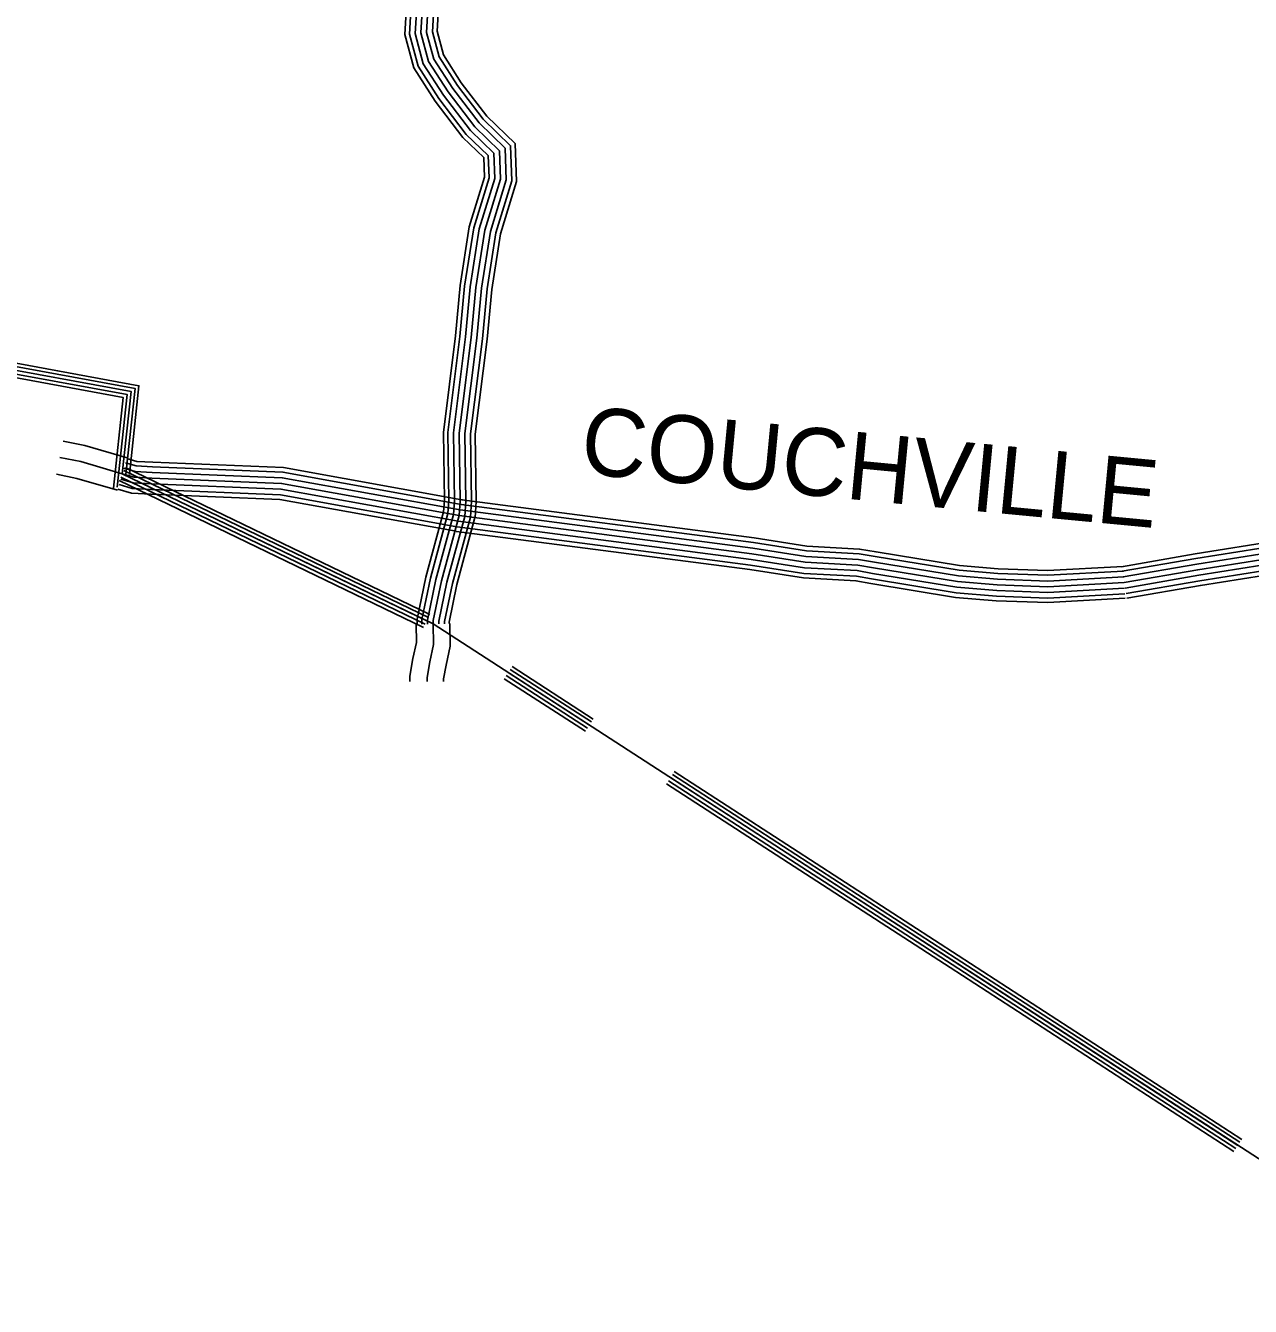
# Model space of a CAD drawing. Extents: x 1788175 to 1969470, y 584502 to 738744.
# Drawn here: x 1829254 to 1835948, y 628222 to 635221 of the extents above; entities that cross this region are included whole.
import ezdxf

# ---------------------------------------------------------------- set-up
doc = ezdxf.new("R2010")
doc.units = 0
for name, color, linetype in [('DESIGN - ROW - Right-of-Way and Easement Labels', 7, 'Continuous'), ('SURVEY - CONTOURS - Index with Text', 7, 'Continuous'), ('SURVEY - DRAINAGE - Natural Features', 7, 'Continuous')]:
    doc.layers.add(name, color=color, linetype=linetype)

msp = doc.modelspace()

# ---------------------------------------------------------------- linework, layer by layer
at = {"layer": 'SURVEY - CONTOURS - Index with Text'}
for points in [[(1831684.4, 632535.7), (1831691.1, 632621.7), (1831685.8, 632990.2), (1831750.6, 633509.5), (1831776, 633782.8), (1831824.1, 634089), (1831911.3, 634373.6), (1831904.6, 634564.9), (1831755, 634709.7), (1831613.8, 634894.6), (1831513.1, 635051.2), (1831476.8, 635187.8), (1831491.4, 635441.6)], [(1831709.9, 632532.3), (1831716.8, 632620.9), (1831711.5, 632988.8), (1831776.2, 633506.8), (1831801.5, 633779.6), (1831849.3, 634083.2), (1831937.1, 634370.2), (1831930, 634576.2), (1831774.3, 634726.9), (1831634.9, 634909.4), (1831536.9, 635061.7), (1831502.7, 635190.4), (1831517.7, 635449.9)], [(1831537.4, 632563.9), (1831542.3, 632626.4), (1831536.9, 632998.4), (1831602.7, 633525.6), (1831628.4, 633801.3), (1831678.8, 634122.5), (1831761.8, 634393.3), (1831758.1, 634499.8), (1831643.6, 634610.6), (1831492, 634809.1), (1831375.4, 634990.4), (1831327, 635172.6), (1831339.7, 635393.6)], [(1831561.5, 632554.4), (1831567, 632625.6), (1831561.7, 632997), (1831627.3, 633523), (1831652.9, 633798.2), (1831703, 634116.9), (1831786.6, 634390), (1831782.4, 634510.6), (1831662.1, 634627.1), (1831512.3, 634823.3), (1831398.3, 635000.5), (1831351.9, 635175.1), (1831364.9, 635401.6)], [(1831592.1, 632549), (1831598, 632624.7), (1831592.7, 632995.3), (1831658.1, 633519.6), (1831683.7, 633794.3), (1831733.3, 634109.9), (1831817.8, 634385.9), (1831813, 634524.2), (1831685.3, 634647.7), (1831537.6, 634841.1), (1831427, 635013.2), (1831383.1, 635178.3), (1831396.5, 635411.6)], [(1831622.8, 632543.7), (1831629.1, 632623.7), (1831623.7, 632993.6), (1831688.9, 633516.2), (1831714.4, 633790.5), (1831763.6, 634103), (1831848.9, 634381.8), (1831843.5, 634537.7), (1831708.6, 634668.4), (1831563, 634858.9), (1831455.7, 635025.9), (1831414.4, 635181.5), (1831428.2, 635421.6)], [(1831622.8, 632543.7), (1831629.1, 632623.7), (1831623.7, 632993.6), (1831688.9, 633516.2), (1831714.4, 633790.5), (1831763.6, 634103), (1831848.9, 634381.8), (1831843.5, 634537.7), (1831708.6, 634668.4), (1831563, 634858.9), (1831455.7, 635025.9), (1831414.4, 635181.5), (1831428.2, 635421.6)], [(1831653.5, 632538.4), (1831660.1, 632622.7), (1831654.8, 632991.9), (1831719.8, 633512.9), (1831745.2, 633786.7), (1831793.8, 634096), (1831880.1, 634377.7), (1831874.1, 634551.3), (1831731.8, 634689.1), (1831588.4, 634876.8), (1831484.4, 635038.5), (1831445.6, 635184.6), (1831459.8, 635431.6)], [(1829458.2, 632950.6), (1829577.6, 632926.8), (1829807.7, 632859.1)], [(1829440.5, 632861.6), (1829555.9, 632838.6), (1829782.1, 632772)], [(1829806.6, 632855.2), (1829861.1, 632839.2), (1829948.2, 632834.6), (1830662.2, 632805.8), (1831637.9, 632629.1)], [(1829790.9, 632801.8), (1829851.6, 632783.9), (1829945.6, 632778.9), (1830656, 632750.3), (1831628, 632574.3)], [(1829799.6, 632831.5), (1829856.9, 632814.7), (1829947, 632809.9), (1830659.5, 632781.2), (1831633.5, 632604.8)], [(1829422.1, 632769.1), (1829533.4, 632747), (1829755.5, 632681.6)], [(1829764.6, 632712.6), (1829835.8, 632691.6), (1829941.2, 632686), (1830645.8, 632657.6), (1831611.4, 632482.8)], [(1829773.4, 632742.3), (1829841.1, 632722.4), (1829942.7, 632717), (1830649.2, 632688.5), (1831616.9, 632513.3)], [(1829782.1, 632772), (1829846.3, 632753.1), (1829944.1, 632748), (1830652.6, 632719.4), (1831622.4, 632543.8)], [(1829782.1, 632772), (1829846.3, 632753.1), (1829944.1, 632748), (1830652.6, 632719.4), (1831622.4, 632543.8)], [(1841380.2, 632093.3), (1840922.1, 632170.4), (1840362.2, 632274.4), (1840090.4, 632334.8), (1839883.1, 632440.9), (1839700.9, 632519), (1839594.2, 632542.1), (1839454.9, 632534.9), (1839250.1, 632485.8), (1838878.8, 632342.6), (1838808, 632325.5), (1838675.8, 632331.9), (1838556, 632355.9), (1838187.8, 632548.5), (1837854.1, 632680.8), (1837731.3, 632713.8), (1837557.4, 632724.3), (1837402.1, 632698.8), (1837098.5, 632599.5), (1836637.1, 632513.8), (1836103.9, 632406.8), (1835646.4, 632334.4), (1835243.3, 632264.3)], [(1829757.4, 632687.9), (1829831.4, 632666.1), (1829940, 632660.3), (1830643, 632632), (1831606.8, 632457.5)], [(1841376.3, 632067.9), (1840917.6, 632145.1), (1840357, 632249.2), (1840081.6, 632310.4), (1839872.1, 632417.6), (1839693.1, 632494.4), (1839592.1, 632516.2), (1839458.6, 632509.3), (1839257.7, 632461.1), (1838886.4, 632318), (1838810.4, 632299.6), (1838672.7, 632306.3), (1838547.3, 632331.4), (1838177.1, 632525.1), (1837846, 632656.3), (1837727.1, 632688.3), (1837558.7, 632698.5), (1837408.2, 632673.8), (1837104.9, 632574.6), (1836641.9, 632488.6), (1836108.5, 632381.4), (1835650.6, 632309), (1835247.7, 632238.9)], [(1841371.5, 632037.3), (1840912.2, 632114.6), (1840350.8, 632218.8), (1840071, 632281), (1839859, 632389.6), (1839683.6, 632464.7), (1839589.6, 632485.1), (1839463.1, 632478.5), (1839267, 632431.5), (1838895.7, 632288.3), (1838813.4, 632268.4), (1838668.9, 632275.4), (1838536.9, 632301.9), (1838164.1, 632496.8), (1837836.3, 632626.9), (1837722.1, 632657.5), (1837560.3, 632667.3), (1837415.6, 632643.6), (1837112.6, 632544.5), (1836647.8, 632458.2), (1836113.9, 632350.9), (1835655.7, 632278.4), (1835253, 632208.4)], [(1835256.6, 632208.8), (1834840.4, 632185.9), (1834565.1, 632195.2), (1834351.7, 632213.6), (1833892.7, 632289), (1833805.4, 632304.3), (1833517.8, 632319.8), (1833228, 632365.1), (1831628.1, 632574.3), (1831629.2, 632574)], [(1835254.9, 632239.7), (1834840, 632217), (1834567, 632226.2), (1834355.5, 632244.4), (1833897.9, 632319.5), (1833808.9, 632335.1), (1833521, 632350.6), (1833232.4, 632395.8), (1831633.4, 632604.9), (1831635.7, 632604.4)], [(1835253.5, 632265.4), (1834839.8, 632242.7), (1834568.5, 632251.8), (1834358.7, 632270), (1833902.2, 632344.9), (1833811.8, 632360.7), (1833523.7, 632376.3), (1833236, 632421.2), (1831637.7, 632630.2), (1831641.1, 632629.5)], [(1835258.3, 632177.8), (1835660.7, 632247.8), (1836119.4, 632320.4), (1836653.7, 632427.7), (1837120.3, 632514.4), (1837422.9, 632613.4), (1837561.9, 632636.2), (1837717.1, 632626.8), (1837826.5, 632597.4), (1838151.2, 632468.6), (1838526.4, 632272.4), (1838665, 632244.6), (1838816.3, 632237.2), (1838905, 632258.7), (1839276.2, 632401.8), (1839467.5, 632447.7), (1839587.1, 632453.9), (1839674.1, 632435.1), (1839845.8, 632361.5), (1840060.5, 632251.6), (1840344.6, 632188.5), (1840906.8, 632084.1), (1841366.8, 632006.6)], [(1841366.8, 632006.6), (1840906.8, 632084.1), (1840344.6, 632188.5), (1840060.5, 632251.6), (1839845.8, 632361.5), (1839674.1, 632435.1), (1839587.1, 632453.9), (1839467.5, 632447.7), (1839276.2, 632401.8), (1838905, 632258.7), (1838816.3, 632237.2), (1838665, 632244.6), (1838526.4, 632272.4), (1838151.2, 632468.6), (1837826.5, 632597.4), (1837717.1, 632626.8), (1837561.9, 632636.2), (1837422.9, 632613.4), (1837120.3, 632514.4), (1836653.7, 632427.7), (1836119.4, 632320.4), (1835660.7, 632247.8), (1835258.3, 632177.8)], [(1841362.1, 631976), (1840901.4, 632053.5), (1840338.4, 632158.1), (1840049.9, 632222.2), (1839832.6, 632333.4), (1839664.6, 632405.4), (1839584.6, 632422.7), (1839472, 632416.9), (1839285.4, 632372.2), (1838914.2, 632229), (1838819.3, 632206.1), (1838661.2, 632213.7), (1838516, 632242.8), (1838138.3, 632440.4), (1837816.7, 632567.9), (1837712.1, 632596), (1837563.5, 632605), (1837430.3, 632583.2), (1837127.9, 632484.3), (1836659.6, 632397.3), (1836124.9, 632289.9), (1835665.8, 632217.2), (1835263.6, 632147.3)], [(1841357.3, 631945.4), (1840896, 632023), (1840332.2, 632127.7), (1840039.3, 632192.8), (1839819.4, 632305.3), (1839655.2, 632375.7), (1839582, 632391.6), (1839476.4, 632386.1), (1839294.7, 632342.5), (1838923.5, 632199.4), (1838822.3, 632174.9), (1838657.4, 632182.9), (1838505.6, 632213.3), (1838125.3, 632412.2), (1837807, 632538.4), (1837707.1, 632565.3), (1837565.1, 632573.9), (1837437.7, 632553), (1837135.6, 632454.1), (1836665.5, 632366.8), (1836130.4, 632259.4), (1835670.9, 632186.7), (1835269, 632116.8)], [(1831537.4, 632563.9), (1831440.9, 632207.3), (1831393.6, 631977.8), (1831394.1, 631949.9)], [(1831561.5, 632554.4), (1831465.9, 632201.4), (1831419.4, 631975.4), (1831419.8, 631950.4)], [(1831592.1, 632549), (1831496.1, 632194.2), (1831450.4, 631972.5), (1831450.8, 631950.9)], [(1831622.8, 632543.7), (1831526.3, 632187), (1831481.5, 631969.6), (1831481.8, 631951.4)], [(1831622.8, 632543.7), (1831526.3, 632187), (1831481.5, 631969.6), (1831481.8, 631951.4)], [(1831653.5, 632538.4), (1831556.5, 632179.8), (1831512.6, 631966.7), (1831512.8, 631952)], [(1831684.9, 632535.6), (1831586.6, 632172.6), (1831543.6, 631963.8), (1831543.8, 631952.5)], [(1831709.6, 632532.4), (1831610.7, 632166.9), (1831568.4, 631961.5), (1831568.5, 631953)], [(1835260, 632146.9), (1834841, 632123.9), (1834561.4, 632133.3), (1834344, 632152.1), (1833882.3, 632227.8), (1833798.3, 632242.6), (1833511.3, 632258), (1833219.2, 632303.7), (1831617.6, 632513.1), (1831616.2, 632513.4)], [(1831622.7, 632543.7), (1831622.8, 632543.7), (1833223.6, 632334.4), (1833514.5, 632288.9), (1833801.9, 632273.4), (1833887.5, 632258.4), (1834347.8, 632182.9), (1834563.2, 632164.3), (1834840.7, 632154.9), (1835258.3, 632177.8)], [(1835258.3, 632177.8), (1834840.7, 632154.9), (1834563.2, 632164.3), (1834347.8, 632182.9), (1833887.5, 632258.4), (1833801.9, 632273.4), (1833514.5, 632288.9), (1833223.6, 632334.4), (1831622.8, 632543.7), (1831622.7, 632543.7)], [(1841353.5, 631920.9), (1840891.6, 631998.7), (1840327.3, 632103.5), (1840030.8, 632169.4), (1839808.9, 632283), (1839647.6, 632352.1), (1839580, 632366.7), (1839480, 632361.5), (1839302, 632318.8), (1838930.9, 632175.7), (1838824.6, 632150), (1838654.4, 632158.3), (1838497.2, 632189.8), (1838115, 632389.7), (1837799.2, 632514.9), (1837703.1, 632540.8), (1837566.3, 632549), (1837443.6, 632528.9), (1837141.7, 632430.1), (1836670.2, 632342.6), (1836134.7, 632235), (1835674.9, 632162.3), (1835273.2, 632092.4)], [(1835263.1, 632091.3), (1834841.6, 632068.1), (1834558.1, 632077.7), (1834337.1, 632096.7), (1833873, 632172.9), (1833792, 632187.1), (1833505.5, 632202.5), (1833211.2, 632248.6), (1831608.5, 632457.2), (1831606.6, 632457.4)], [(1835261.7, 632115.9), (1834841.3, 632092.8), (1834559.5, 632102.3), (1834340.1, 632121.3), (1833877.2, 632197.3), (1833794.8, 632211.7), (1833508, 632227.2), (1833214.8, 632273), (1831612.3, 632482.6), (1831609.7, 632483.1)], [(1831387.5, 631949.8), (1831389.3, 631849.2), (1831370.1, 631762.3), (1831353.1, 631666.1), (1831353.3, 631636.2)], [(1831481.8, 631951.4), (1831483.8, 631839.6), (1831462.6, 631743.9), (1831447.5, 631658.1), (1831447.6, 631636.7)], [(1831572.5, 631953), (1831574.7, 631830.5), (1831551.6, 631726.2), (1831538.2, 631650.5), (1831538.3, 631637.3)]]:
    msp.add_lwpolyline(points, dxfattribs=at)
at = {"layer": 'SURVEY - DRAINAGE - Natural Features'}
for points in [[(1829782.1, 632772), (1829830.5, 633221.2), (1829013.8, 633371), (1828979.6, 633203.5), (1824515, 636888.2), (1820759.6, 639992.6)], [(1827489.1, 634459.6), (1828966.7, 633240.1), (1828998.1, 633394.2), (1829852.4, 633237.5), (1829802, 632769.9)], [(1827501.1, 634474.2), (1828954.4, 633274.9), (1828983.2, 633416.3), (1829873.2, 633253), (1829820.9, 632767.9)], [(1827450.9, 634413.3), (1829005.5, 633130.2), (1829045.1, 633324.6), (1829786.8, 633188.5), (1829733.4, 632693.3)], [(1827463.6, 634428.7), (1828992.6, 633166.9), (1829029.4, 633347.8), (1829808.6, 633204.8), (1829754.1, 632698.7)], [(1827476.3, 634444.2), (1828979.6, 633203.5), (1829013.8, 633371), (1829830.5, 633221.2), (1829782.1, 632772)], [(1829790.8, 632790.1), (1831455, 631986.6)], [(1829799.1, 632807.2), (1831463.3, 632003.7)], [(1829764.7, 632736), (1831428.9, 631932.6)], [(1829773.4, 632754), (1831437.6, 631950.6)], [(1829782.1, 632772), (1831481.8, 631951.4), (1836379.9, 628777.5), (1836210.1, 628313.7), (1836181.7, 628221.6)], [(1829782.1, 632772), (1831446.3, 631968.6)], [(1831881, 631669), (1832324.1, 631381.8)], [(1831891.9, 631685.7), (1832334.9, 631398.6)], [(1831902.7, 631702.5), (1832345.8, 631415.4)], [(1831913.1, 631718.5), (1832356.2, 631431.3)], [(1831870.1, 631652.2), (1832313.2, 631365)], [(1832778, 631111.5), (1834328.9, 630106.5)], [(1832788.9, 631128.3), (1834339.8, 630123.3)], [(1832799.3, 631144.2), (1834350.1, 630139.2)], [(1832756.3, 631077.9), (1834307.2, 630073)], [(1832767.2, 631094.7), (1834318, 630089.7)], [(1834339.8, 630123.3), (1835890.6, 629118.4)], [(1834350.1, 630139.2), (1835901, 629134.3)], [(1834307.2, 630073), (1835858, 629068)], [(1834318, 630089.7), (1835868.9, 629084.8)], [(1834328.9, 630106.5), (1835879.8, 629101.6)]]:
    msp.add_lwpolyline(points, dxfattribs=at)

# ---------------------------------------------------------------- texts
at = {"layer": 'DESIGN - ROW - Right-of-Way and Easement Labels'}
msp.add_text('COUCHVILLE', height=370, rotation=354.56912, dxfattribs=at).set_placement((1832278, 632774.4))

doc.saveas('drawing.dxf')
